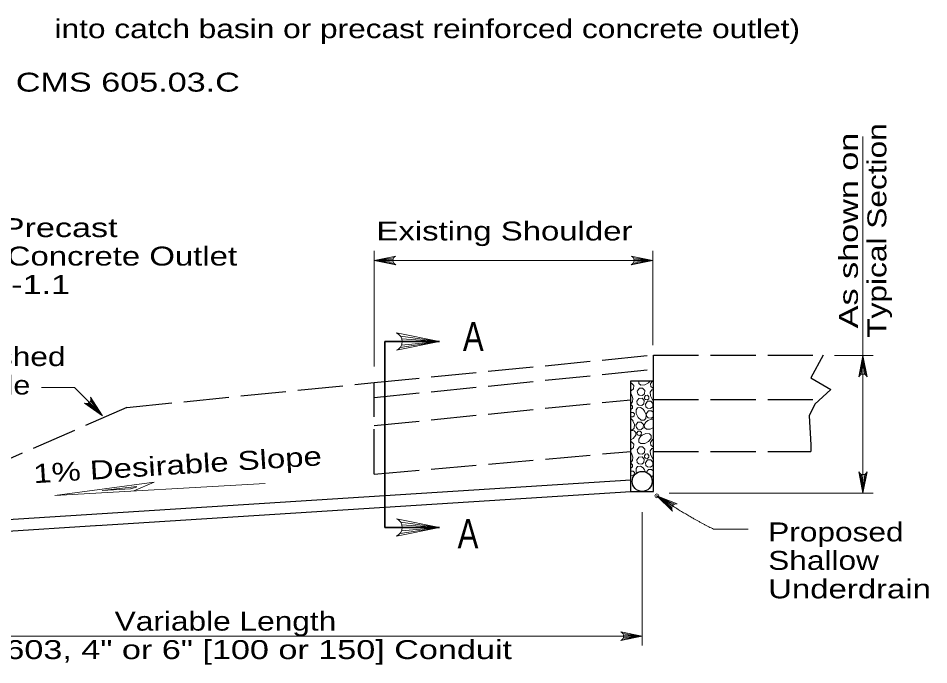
# Model space of a CAD drawing. Extents: x 743.9 to 777.9, y 1051 to 1073.
# Drawn here: x 748.95 to 756.46, y 1061.12 to 1066.45 of the extents above; entities that cross this region are included whole.
import ezdxf
from ezdxf.enums import TextEntityAlignment as Align

# ---------------------------------------------------------------- set-up
doc = ezdxf.new("R2010")
doc.units = 0
doc.header["$LTSCALE"] = 0.062
doc.header["$PDMODE"] = 32
doc.header["$PDSIZE"] = 0.031
doc.linetypes.add('LONG_DASHED', pattern=[7.5, 6, -1.5])
doc.linetypes.add('MEDIUM_DASHED', pattern=[4.5, 3, -1.5])
doc.layers.add('1', color=7, linetype='Continuous', lineweight=13)

msp = doc.modelspace()

# ---------------------------------------------------------------- linework, layer by layer
at = {"layer": '1'}
for p, q in [((755.91825, 1062.5385), (755.91825, 1065.47817)), ((751.88925, 1063.58192), (751.88925, 1064.53658)), ((754.18483, 1063.75892), (754.18483, 1064.53658)), ((752.04942, 1064.47967), (751.88925, 1064.45725)), ((752.044, 1064.46858), (751.88925, 1064.45725)), ((751.88925, 1064.45725), (754.18483, 1064.45725)), ((752.04242, 1064.45725), (751.88925, 1064.45725)), ((752.04517, 1064.44283), (751.88925, 1064.45725)), ((752.05133, 1064.43242), (751.88925, 1064.45725)), ((754.02275, 1064.43242), (754.18483, 1064.45725)), ((754.02458, 1064.47967), (754.18483, 1064.45725)), ((754.02883, 1064.44283), (754.18483, 1064.45725)), ((754.03008, 1064.46858), (754.18483, 1064.45725)), ((754.03167, 1064.45725), (754.18483, 1064.45725)), ((752.10575, 1063.83283), (752.42625, 1063.788)), ((752.11667, 1063.81067), (752.42625, 1063.788)), ((752.102, 1063.73842), (752.42625, 1063.788)), ((752.11425, 1063.75925), (752.42625, 1063.788)), ((752.11992, 1063.788), (752.42625, 1063.788)), ((755.68408, 1063.6735), (756.00317, 1063.6735)), ((755.8935, 1063.51133), (755.91825, 1063.6735)), ((755.90392, 1063.5175), (755.91825, 1063.6735)), ((755.91825, 1063.52033), (755.91825, 1063.6735)), ((755.92958, 1063.51867), (755.91825, 1063.6735)), ((755.94067, 1063.51325), (755.91825, 1063.6735)), ((754.00875, 1063.46475), (754.00342, 1063.46208)), ((749.14575, 1063.40875), (749.41875, 1063.40875)), ((749.64825, 1063.17675), (749.41875, 1063.40875)), ((749.54183, 1063.28692), (749.64825, 1063.17675)), ((749.55025, 1063.299), (749.64825, 1063.17675)), ((749.55342, 1063.31058), (749.64825, 1063.17675)), ((754.00342, 1063.35817), (754.01017, 1063.34967)), ((749.52083, 1063.2765), (749.64825, 1063.17675)), ((749.53258, 1063.28025), (749.64825, 1063.17675)), ((754.00342, 1062.87483), (754.01017, 1062.86633)), ((754.11733, 1062.73167), (754.12425, 1062.71425)), ((755.89583, 1062.69875), (755.91825, 1062.5385)), ((755.90692, 1062.69333), (755.91825, 1062.5385)), ((755.94308, 1062.70067), (755.91825, 1062.5385)), ((755.93267, 1062.6945), (755.91825, 1062.5385)), ((755.91825, 1062.69167), (755.91825, 1062.5385)), ((754.32108, 1062.53908), (756.00317, 1062.53908)), ((754.30442, 1062.46133), (754.21833, 1062.51625)), ((754.34767, 1062.43408), (754.21833, 1062.51625)), ((754.34233, 1062.42042), (754.21833, 1062.51625)), ((754.34192, 1062.40842), (754.21833, 1062.51625)), ((754.35508, 1062.44275), (754.21833, 1062.51625)), ((754.36567, 1062.44925), (754.21833, 1062.51625)), ((754.09783, 1061.28242), (754.09783, 1062.38108)), ((752.102, 1062.20642), (752.42625, 1062.256)), ((752.10575, 1062.30083), (752.42625, 1062.256)), ((752.11425, 1062.22717), (752.42625, 1062.256)), ((752.11667, 1062.27858), (752.42625, 1062.256)), ((752.11992, 1062.256), (752.42625, 1062.256)), ((754.68675, 1062.24175), (754.9725, 1062.24175)), ((747.35933, 1061.36017), (754.09783, 1061.36017)), ((753.93575, 1061.33542), (754.09783, 1061.36017)), ((753.93758, 1061.38258), (754.09783, 1061.36017)), ((753.94183, 1061.34583), (754.09783, 1061.36017)), ((753.943, 1061.3715), (754.09783, 1061.36017)), ((753.94467, 1061.36017), (754.09783, 1061.36017))]:
    msp.add_line(p, q, dxfattribs=at)
at = {"layer": '1', "linetype": 'LONG_DASHED', "lineweight": 25}
for p, q in [((754.19, 1063.67733), (755.59025, 1063.67733)), ((751.88925, 1063.32708), (754.19025, 1063.55925)), ((751.88925, 1062.69475), (751.88925, 1063.45067)), ((751.88925, 1063.09583), (754.00342, 1063.30917)), ((754.19, 1063.30942), (755.53842, 1063.30942)), ((749.85042, 1063.24492), (747.08767, 1062.03908)), ((751.88925, 1062.69475), (754.00342, 1062.88225)), ((754.19, 1062.88225), (755.48908, 1062.88225))]:
    msp.add_line(p, q, dxfattribs=at)
at = {"layer": '1', "lineweight": 25}
for p, q in [((754.19, 1063.46475), (754.19, 1063.67733)), ((754.00342, 1062.55325), (754.00342, 1063.46475)), ((754.00342, 1063.46475), (754.19, 1063.46475)), ((754.19, 1062.55325), (754.19, 1063.46475)), ((747.53925, 1062.23575), (754.00342, 1062.64917)), ((749.60317, 1062.27233), (754.00342, 1062.55325)), ((754.00342, 1062.55325), (754.19, 1062.55325)), ((747.29233, 1062.12783), (749.631, 1062.27417))]:
    msp.add_line(p, q, dxfattribs=at)
at = {"layer": '1', "linetype": 'MEDIUM_DASHED', "lineweight": 25}
msp.add_line((755.48908, 1062.93642), (755.48908, 1062.88225), dxfattribs=at)
at = {"layer": '1'}
for points in [[(752.06625, 1064.42183), (751.88925, 1064.45725), (752.06625, 1064.49258)], [(754.00783, 1064.42183), (754.18483, 1064.45725), (754.00783, 1064.49258)], [(752.07225, 1063.71717), (752.42625, 1063.788), (752.07225, 1063.85883)], [(755.88292, 1063.4965), (755.91825, 1063.6735), (755.95367, 1063.4965)], [(754.00342, 1063.44542), (754.01033, 1063.44592), (754.02892, 1063.42633), (754.02633, 1063.39908), (754.00958, 1063.38517), (754.00342, 1063.38558)], [(754.16483, 1063.46475), (754.15075, 1063.44675), (754.11842, 1063.4305), (754.08775, 1063.43), (754.07058, 1063.44225), (754.06908, 1063.46475)], [(754.19, 1063.406), (754.18267, 1063.40658), (754.17, 1063.41867), (754.16592, 1063.43967), (754.18292, 1063.46375), (754.19, 1063.46417)], [(754.19, 1063.30258), (754.18167, 1063.30917), (754.16533, 1063.34158), (754.16483, 1063.372), (754.17717, 1063.38925), (754.19, 1063.39008)], [(749.55075, 1063.32867), (749.64825, 1063.17675), (749.49983, 1063.2795)], [(754.00933, 1063.35108), (754.02192, 1063.3195), (754.01942, 1063.29017), (754.00625, 1063.27642), (754.00342, 1063.27642)], [(754.05258, 1063.29567), (754.06958, 1063.31975), (754.09667, 1063.32125), (754.11558, 1063.30192), (754.11275, 1063.27458), (754.09608, 1063.26067), (754.06942, 1063.26258), (754.05675, 1063.27467), (754.05275, 1063.29567)], [(754.00342, 1063.26642), (754.00825, 1063.26675), (754.01942, 1063.25508), (754.01775, 1063.23867), (754.00775, 1063.23042), (754.00342, 1063.23067)], [(754.11733, 1063.21475), (754.12983, 1063.18325), (754.12742, 1063.15408), (754.11442, 1063.14025), (754.09067, 1063.14075), (754.06383, 1063.16175), (754.04767, 1063.19417), (754.04708, 1063.22467), (754.0595, 1063.24192), (754.08375, 1063.24358), (754.10542, 1063.22958), (754.11825, 1063.21358)], [(754.19, 1063.16992), (754.17508, 1063.1575), (754.14833, 1063.15942), (754.13592, 1063.17167), (754.13183, 1063.19258), (754.14867, 1063.21658), (754.17583, 1063.21825), (754.19, 1063.20333)], [(754.00342, 1063.199), (754.00625, 1063.20308), (754.02242, 1063.20408), (754.03375, 1063.1925), (754.03217, 1063.17608), (754.02208, 1063.16767), (754.00608, 1063.16883), (754.00342, 1063.17142)], [(754.00342, 1063.15375), (754.00958, 1063.14958), (754.02242, 1063.13367)], [(754.02167, 1063.13492), (754.03425, 1063.10325), (754.03167, 1063.07417), (754.01858, 1063.06042), (754.00342, 1063.06075)], [(754.19, 1063.07958), (754.16433, 1063.06683), (754.13375, 1063.06633), (754.11667, 1063.07858), (754.11492, 1063.10292), (754.129, 1063.12458), (754.145, 1063.13742)], [(754.14375, 1063.13667), (754.17517, 1063.14908), (754.19, 1063.14783)], [(754.00342, 1063.0555), (754.03225, 1063.053), (754.04592, 1063.03992), (754.04558, 1063.01625), (754.02467, 1062.98942), (754.00342, 1062.97883)], [(754.09758, 1063.017), (754.12925, 1063.02958), (754.15833, 1063.02708), (754.17217, 1063.01392), (754.17175, 1062.99042), (754.15075, 1062.9635), (754.11842, 1062.94733), (754.08775, 1062.94675), (754.07058, 1062.95883), (754.069, 1062.98333), (754.08292, 1063.00508), (754.09892, 1063.01775)], [(754.00342, 1062.96208), (754.01033, 1062.96267), (754.02892, 1062.94308), (754.02633, 1062.91575), (754.00958, 1062.90192), (754.00342, 1062.90233)], [(754.19, 1062.92275), (754.18267, 1062.92333), (754.17, 1062.93542), (754.16592, 1062.95642), (754.18292, 1062.9805), (754.19, 1062.98092)], [(754.00933, 1062.86767), (754.02192, 1062.83608), (754.01942, 1062.80692), (754.00625, 1062.79317), (754.00342, 1062.79325)], [(754.05258, 1062.81242), (754.06958, 1062.83642), (754.09667, 1062.838), (754.11558, 1062.8185), (754.11275, 1062.79125), (754.09608, 1062.77742), (754.06942, 1062.77925), (754.05675, 1062.79142), (754.05275, 1062.81242)], [(754.19, 1062.81933), (754.18167, 1062.82575), (754.16533, 1062.85833), (754.16483, 1062.88883), (754.17717, 1062.906), (754.19, 1062.90683)], [(754.00342, 1062.78317), (754.00825, 1062.7835), (754.01942, 1062.77183), (754.01775, 1062.75542), (754.00775, 1062.74708), (754.00342, 1062.74742)], [(754.05075, 1062.70467), (754.04767, 1062.71083), (754.04708, 1062.74142), (754.0595, 1062.75858), (754.08375, 1062.76025), (754.10542, 1062.74642), (754.11825, 1062.73025)], [(754.00342, 1062.71575), (754.00625, 1062.71983), (754.02242, 1062.72092), (754.03375, 1062.70908), (754.03217, 1062.69267), (754.02208, 1062.68442), (754.00608, 1062.68558), (754.00342, 1062.68817)], [(754.13292, 1062.71108), (754.14867, 1062.73333), (754.17583, 1062.735), (754.19, 1062.72017)], [(754.19, 1062.68667), (754.17508, 1062.67425), (754.17183, 1062.6745)], [(755.95367, 1062.7155), (755.91825, 1062.5385), (755.88292, 1062.7155)], [(750.98975, 1062.61767), (749.2565, 1062.5185), (750.075, 1062.62808), (749.90742, 1062.55833)], [(749.93283, 1062.59375), (749.6465, 1062.56167), (749.87933, 1062.575), (749.92817, 1062.58825)], [(754.34875, 1062.39142), (754.21833, 1062.51625), (754.38675, 1062.45117)], [(752.07225, 1062.18517), (752.42625, 1062.256), (752.07225, 1062.32675)], [(753.92083, 1061.32475), (754.09783, 1061.36017), (753.92083, 1061.39558)]]:
    msp.add_lwpolyline(points, dxfattribs=at)
at = {"layer": '1', "lineweight": 35}
msp.add_lwpolyline([(752.42625, 1062.256), (751.97742, 1062.256), (751.97742, 1063.788), (752.42625, 1063.788)], dxfattribs=at)
at = {"layer": '1', "linetype": 'LONG_DASHED', "lineweight": 25}
for points in [[(749.85042, 1063.24492), (751.88925, 1063.45067), (754.19, 1063.67733)], [(755.59025, 1063.67733), (755.48908, 1063.4885), (755.65333, 1063.3925), (755.52042, 1063.2725), (755.47342, 1063.1765), (755.48908, 1062.93642)]]:
    msp.add_lwpolyline(points, dxfattribs=at)
at = {"layer": '1'}
for points in [[(754.0575, 1063.37925), (754.07442, 1063.40342), (754.10142, 1063.40492), (754.12017, 1063.3855), (754.1175, 1063.35808), (754.10075, 1063.34425), (754.07417, 1063.34625), (754.06158, 1063.35833)], [(754.11567, 1063.32983), (754.12567, 1063.34442), (754.142, 1063.34542), (754.15325, 1063.3335), (754.15175, 1063.31717), (754.14158, 1063.30892), (754.12567, 1063.31), (754.11817, 1063.31742)], [(754.12425, 1063.27175), (754.14117, 1063.29575), (754.16817, 1063.29733), (754.187, 1063.27783), (754.18433, 1063.25058), (754.16767, 1063.23675), (754.14092, 1063.23867), (754.12833, 1063.25092)], [(754.04592, 1063.09942), (754.06283, 1063.1235), (754.09008, 1063.12508), (754.10875, 1063.10558), (754.106, 1063.07825), (754.08933, 1063.06442), (754.06258, 1063.06642), (754.05017, 1063.07858)], [(754.05383, 1063.03558), (754.06383, 1063.04983), (754.08008, 1063.05092), (754.09125, 1063.03917), (754.08983, 1063.02283), (754.07967, 1063.0145), (754.06375, 1063.01567), (754.05617, 1063.023)], [(754.0575, 1062.896), (754.07442, 1062.92017), (754.10142, 1062.9215), (754.12017, 1062.90217), (754.1175, 1062.87483), (754.10075, 1062.86092), (754.07417, 1062.863), (754.06158, 1062.87508)], [(754.11567, 1062.84658), (754.12567, 1062.86117), (754.142, 1062.862), (754.15325, 1062.85033), (754.15175, 1062.83408), (754.14158, 1062.82567), (754.12567, 1062.82675), (754.11817, 1062.83417)], [(754.12425, 1062.78842), (754.14117, 1062.8125), (754.16817, 1062.81408), (754.187, 1062.7945), (754.18433, 1062.76733), (754.16767, 1062.7535), (754.14092, 1062.75542), (754.12833, 1062.7675)]]:
    msp.add_lwpolyline(points, close=True, dxfattribs=at)
at = {"layer": '1', "lineweight": 25}
msp.add_circle((754.09778, 1062.63585), 0.0826, dxfattribs=at)
at = {"layer": '1'}
for centre, radius, start, end in [((752.08051, 1064.45726), 0.0382, 112.08782, 247.91395), ((753.99357, 1064.45726), 0.0382, 292.08605, 67.91218), ((752.04368, 1063.78808), 0.0764, 292.08605, 67.91218), ((755.91832, 1063.48217), 0.0382, 22.08782, 157.91395), ((749.51533, 1063.31435), 0.0382, 246.08289, 21.90901), ((755.91824, 1062.72983), 0.0382, 202.08782, 337.91395), ((754.37983, 1062.41369), 0.0382, 79.64546, 215.47159), ((752.04368, 1062.25605), 0.0764, 292.08605, 67.91218), ((753.90656, 1061.36023), 0.0382, 292.08605, 67.91218)]:
    msp.add_arc(centre, radius, start, end, dxfattribs=at)
msp.add_open_spline([(754.21833, 1062.51625), (754.49092, 1062.33758), (754.68675, 1062.24175)], degree=2, dxfattribs=at)
msp.add_point((754.21833, 1062.51625), dxfattribs=at)

# ---------------------------------------------------------------- texts
for s, height, width, p in [('into catch basin or precast reinforced concrete outlet)', 0.156, 1.25, (749.25317, 1066.28917)), ('Backfill as per CMS 605.03.C', 0.156, 1.35, (747.10283, 1065.84833)), ('Item 604 - Precast', 0.156, 1.35, (747.47217, 1064.64933)), ('Existing Shoulder', 0.156, 1.3, (751.90717, 1064.6215)), ('Reinforced Concrete Outlet', 0.156, 1.3, (747.47217, 1064.41467)), ('    SCD DM-1.1 ', 0.156, 1.35, (747.47217, 1064.18)), ('A', 0.24, 0.8, (752.61983, 1063.7105)), ('Finished', 0.156, 1.25, (748.358, 1063.58642)), ('Grade', 0.156, 1.2, (748.358, 1063.35175)), ('A', 0.24, 0.8, (752.57633, 1062.08425)), ('Proposed', 0.156, 1.25, (755.13667, 1062.14092)), ('Shallow', 0.156, 1.25, (755.13667, 1061.90625)), ('Underdrain', 0.156, 1.3, (755.13667, 1061.67158))]:
    msp.add_text(s, height=height, dxfattribs=dict(at, width=width)).set_placement(p)
for s, width, p in [('Typical Section', 1.25, (756.11083, 1064.70383)), ('As shown on', 1.35, (755.87617, 1064.70379))]:
    msp.add_text(s, height=0.156, rotation=90, dxfattribs=dict(at, width=width)).set_placement(p, align=Align.CENTER)
at = {"layer": '1', "width": 1.3}
msp.add_text('1% Desirable Slope', height=0.156, rotation=3.576, dxfattribs=at).set_placement((749.083, 1062.62025))
at = {"layer": '1'}
for s, width, p in [('Variable Length', 1.25, (750.66229, 1061.40567)), ('Item 603, 4" or 6" [100 or 150] Conduit ', 1.35, (750.66225, 1061.171))]:
    msp.add_text(s, height=0.156, dxfattribs=dict(at, width=width)).set_placement(p, align=Align.CENTER)

doc.saveas('drawing.dxf')
